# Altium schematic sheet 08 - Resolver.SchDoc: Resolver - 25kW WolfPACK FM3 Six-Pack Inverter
size 431 x 279 mm; Date: 07/2023; DocumentNumber: CRD25DA12N-FMC; Revision: 1.1; SheetNumber: 8; SheetTotal: 8; SheetSize: B
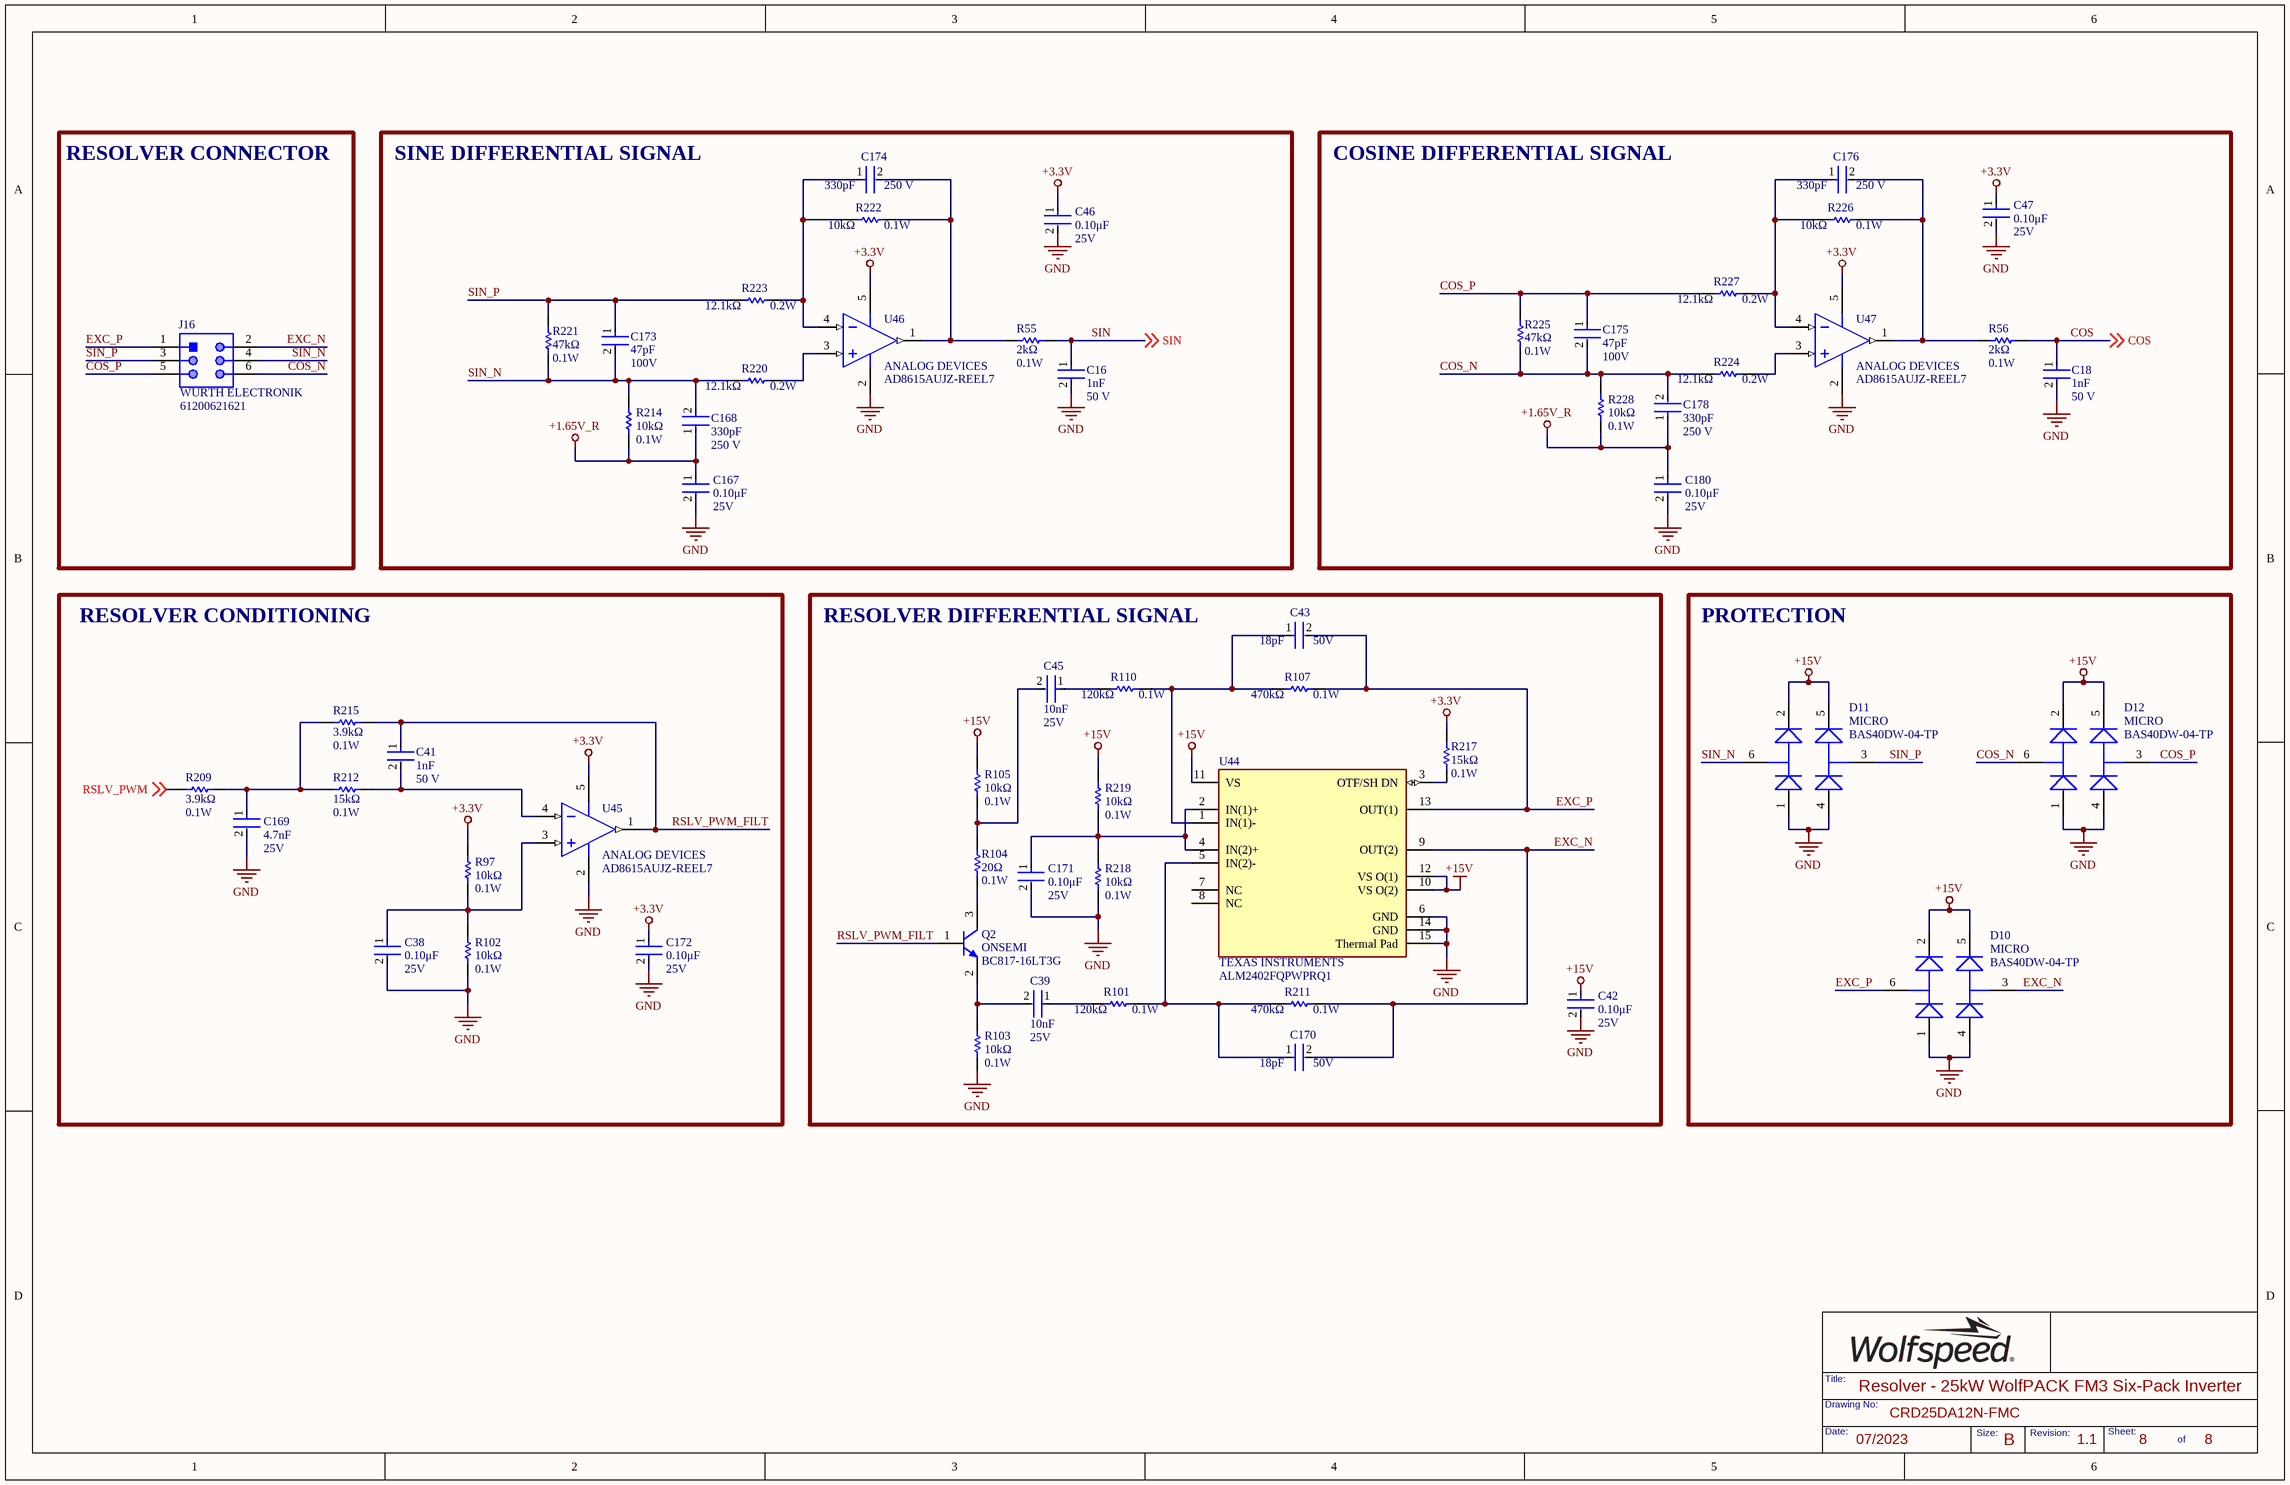
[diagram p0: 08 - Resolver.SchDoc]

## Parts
C16  Capacitance: 1nF  Voltage Rating: 50 V  [FP-C0603C-CF-IPC_B]  (hidden comment: C0603C102K5RACAUTO)
C18  Capacitance: 1nF  Voltage Rating: 50 V  [FP-C0603C-CF-IPC_B]  (hidden comment: C0603C102K5RACAUTO)
C38  Voltage Rating: 25V  Capacitance: 0.10μF  [FP-C0603C-CF-IPC_B]  (hidden comment: C0603C104K3RACTU)
C39  value 10nF  Voltage Rating: 25V  [FP-C0603C-CF-IPC_B]  (hidden comment: CL10B103KA8WPNC)
C41  Capacitance: 1nF  Voltage Rating: 50 V  [FP-C0603C-CF-IPC_B]  (hidden comment: C0603C102K5RACAUTO)
C42  Voltage Rating: 25V  Capacitance: 0.10μF  [FP-C0603C-CF-IPC_B]  (hidden comment: C0603C104K3RACTU)
C43  Capacitance: 18pF  Voltage Rating: 50V  [FP-C0603C-CF-IPC_B]  (hidden comment: 06035A180JAT2A)
C45  value 10nF  Voltage Rating: 25V  [FP-C0603C-CF-IPC_B]  (hidden comment: CL10B103KA8WPNC)
C46  Voltage Rating: 25V  Capacitance: 0.10μF  [FP-C0603C-CF-IPC_B]  (hidden comment: C0603C104K3RACTU)
C47  Voltage Rating: 25V  Capacitance: 0.10μF  [FP-C0603C-CF-IPC_B]  (hidden comment: C0603C104K3RACTU)
C167  Voltage Rating: 25V  Capacitance: 0.10μF  [FP-C0603C-CF-IPC_B]  (hidden comment: C0603C104K3RACTU)
C168  value 330pF  Voltage Rating: 250 V  [FP-C0603C-CF-IPC_B]  (hidden comment: C0603C331JAGAC7867)
C169  Voltage Rating: 25V  Capacitance: 4.7nF  [FP-C0603C-CF-IPC_B]  (hidden comment: C0603C472K3RAC7867)
C170  Capacitance: 18pF  Voltage Rating: 50V  [FP-C0603C-CF-IPC_B]  (hidden comment: 06035A180JAT2A)
C171  Voltage Rating: 25V  Capacitance: 0.10μF  [FP-C0603C-CF-IPC_B]  (hidden comment: C0603C104K3RACTU)
C172  Voltage Rating: 25V  Capacitance: 0.10μF  [FP-C0603C-CF-IPC_B]  (hidden comment: C0603C104K3RACTU)
C173  Capacitance: 47pF  Voltage Rating (DC): 100V  [FP-C0603C-CF-IPC_B]  (hidden comment: C0603C470J1GACTU)
C174  value 330pF  Voltage Rating: 250 V  [FP-C0603C-CF-IPC_B]  (hidden comment: C0603C331JAGAC7867)
C175  Capacitance: 47pF  Voltage Rating (DC): 100V  [FP-C0603C-CF-IPC_B]  (hidden comment: C0603C470J1GACTU)
C176  value 330pF  Voltage Rating: 250 V  [FP-C0603C-CF-IPC_B]  (hidden comment: C0603C331JAGAC7867)
C178  value 330pF  Voltage Rating: 250 V  [FP-C0603C-CF-IPC_B]  (hidden comment: C0603C331JAGAC7867)
C180  Voltage Rating: 25V  Capacitance: 0.10μF  [FP-C0603C-CF-IPC_B]  (hidden comment: C0603C104K3RACTU)
D10  Manufacturer Print: MICRO  [SOT65P222X120-6N]  (hidden comment: BAS40DW-04-TP)
D11  Manufacturer Print: MICRO  [SOT65P222X120-6N]  (hidden comment: BAS40DW-04-TP)
D12  Manufacturer Print: MICRO  [SOT65P222X120-6N]  (hidden comment: BAS40DW-04-TP)
J16  Manufacturer: WURTH ELECTRONIK  [61200621621]  (hidden comment: 61200621621)
Q2  Manufacturer: ONSEMI  [ONSC-SOT-23-3-318-08_V]  (hidden comment: BC817-16LT3G)
R55  Resistance: 2kΩ  Power Rating: 0.1W  [FP-MCR03-IPC_B]  (hidden comment: RT0603DRE072KL)
R56  Resistance: 2kΩ  Power Rating: 0.1W  [FP-MCR03-IPC_B]  (hidden comment: RT0603DRE072KL)
R97  Resistance: 10kΩ  Max Power Dissipation: 0.1W  [FP-MCR03-IPC_B]  (hidden comment: ERJ3EKF1002V)
R101  Max Power Dissipation: 0.1W  Resistance: 120kΩ  [FP-MCR03-IPC_B]  (hidden comment: RC0603FR-07120KL)
R102  Resistance: 10kΩ  Max Power Dissipation: 0.1W  [FP-MCR03-IPC_B]  (hidden comment: ERJ3EKF1002V)
R103  Resistance: 10kΩ  Max Power Dissipation: 0.1W  [FP-MCR03-IPC_B]  (hidden comment: ERJ3EKF1002V)
R104  Resistance: 20Ω  Power Rating: 0.1W  [FP-MCR03-IPC_B]  (hidden comment: RC0603JR-0720RL)
R105  Resistance: 10kΩ  Max Power Dissipation: 0.1W  [FP-MCR03-IPC_B]  (hidden comment: ERJ3EKF1002V)
R107  Resistance: 470kΩ  Power Rating: 0.1W  [FP-MCR03-IPC_B]  (hidden comment: RC0603FR-07470KL)
R110  Max Power Dissipation: 0.1W  Resistance: 120kΩ  [FP-MCR03-IPC_B]  (hidden comment: RC0603FR-07120KL)
R209  Resistance: 3.9kΩ  Power Rating: 0.1W  [FP-MCR03-IPC_B]  (hidden comment: ERJ3EKF3901V)
R211  Resistance: 470kΩ  Power Rating: 0.1W  [FP-MCR03-IPC_B]  (hidden comment: RC0603FR-07470KL)
R212  Resistance: 15kΩ  Power Rating: 0.1W  [FP-MCR03-IPC_B]  (hidden comment: ERA-3AED153V)
R214  Resistance: 10kΩ  Max Power Dissipation: 0.1W  [FP-MCR03-IPC_B]  (hidden comment: ERJ3EKF1002V)
R215  Resistance: 3.9kΩ  Power Rating: 0.1W  [FP-MCR03-IPC_B]  (hidden comment: ERJ3EKF3901V)
R217  Resistance: 15kΩ  Power Rating: 0.1W  [FP-MCR03-IPC_B]  (hidden comment: ERA-3AED153V)
R218  Resistance: 10kΩ  Max Power Dissipation: 0.1W  [FP-MCR03-IPC_B]  (hidden comment: ERJ3EKF1002V)
R219  Resistance: 10kΩ  Max Power Dissipation: 0.1W  [FP-MCR03-IPC_B]  (hidden comment: ERJ3EKF1002V)
R220  Resistance: 12.1kΩ  Max Power Dissipation: 0.2W  [FP-MCR03-IPC_B]  (hidden comment: ERJ-PB3B1212V)
R221  Resistance: 47kΩ  Power Rating: 0.1W  [FP-MCR03-IPC_B]  (hidden comment: RC0603FR-0747KL)
R222  Resistance: 10kΩ  Max Power Dissipation: 0.1W  [FP-MCR03-IPC_B]  (hidden comment: ERJ3EKF1002V)
R223  Resistance: 12.1kΩ  Max Power Dissipation: 0.2W  [FP-MCR03-IPC_B]  (hidden comment: ERJ-PB3B1212V)
R224  Resistance: 12.1kΩ  Max Power Dissipation: 0.2W  [FP-MCR03-IPC_B]  (hidden comment: ERJ-PB3B1212V)
R225  Resistance: 47kΩ  Power Rating: 0.1W  [FP-MCR03-IPC_B]  (hidden comment: RC0603FR-0747KL)
R226  Resistance: 10kΩ  Max Power Dissipation: 0.1W  [FP-MCR03-IPC_B]  (hidden comment: ERJ3EKF1002V)
R227  Resistance: 12.1kΩ  Max Power Dissipation: 0.2W  [FP-MCR03-IPC_B]  (hidden comment: ERJ-PB3B1212V)
R228  Resistance: 10kΩ  Max Power Dissipation: 0.1W  [FP-MCR03-IPC_B]  (hidden comment: ERJ3EKF1002V)
U44  Manufacturer: TEXAS INSTRUMENTS  [FP-PWP0014H-MFG]  (hidden comment: ALM2402FQPWPRQ1)
U45  Manufacturer: ANALOG DEVICES  [ADI-UJ-5_M]  (hidden comment: AD8615AUJZ-REEL7)
U46  Manufacturer: ANALOG DEVICES  [ADI-UJ-5_M]  (hidden comment: AD8615AUJZ-REEL7)
U47  Manufacturer: ANALOG DEVICES  [ADI-UJ-5_M]  (hidden comment: AD8615AUJZ-REEL7)

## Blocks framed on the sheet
RESOLVER CONNECTOR: J16
SINE DIFFERENTIAL SIGNAL: C16 C46 C167 C168 C173 C174 R55 R214 R220-R223 U46
COSINE DIFFERENTIAL SIGNAL: C18 C47 C175 C176 C178 C180 R56 R224-R228 U47
RESOLVER CONDITIONING: C38 C41 C169 C172 R97 R102 R209 R212 R215 U45
RESOLVER DIFFERENTIAL SIGNAL: C39 C42 C43 C45 C170 C171 Q2 R101 R103-R105 R107 R110 R211 R217-R219 U44
PROTECTION: D10-D12

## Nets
+1.65V_R: C167.1 C168.1 C178.1 C180.1 R214.1 R228.1
+3.3V: C46.1 C47.1 C172.1 R97.2 R217.2 U45.5(+V) U46.5(+V) U47.5(+V)
+15V: C42.1 D10.2(C1) D10.5(C2) D11.2(C1) D11.5(C2) D12.2(C1) D12.5(C2) R105.2 R219.2 U44.10(VS_O(2)) U44.11(VS) U44.12(VS_O(1))
GND: C16.2 C18.2 C38.2 C42.2 C46.2 C47.2 C167.2 C169.2 C171.2 C172.2 C180.2 D10.1(A1) D10.4(A2) D11.1(A1) D11.4(A2) D12.1(A1) D12.4(A2) R102.1 R103.1 R218.1 U44.6(GND) U44.14(GND) U44.15(Thermal_Pad) U45.2(-V) U46.2(-V) U47.2(-V)
COS: C18.1 R56.2 ; off-sheet COS
COS_N: C175.2 C178.2 D12.6(AC1) J16.6 R224.1 R225.1 R228.2
COS_P: C175.1 D12.3(AC2) J16.5 R225.2 R227.1
EXC_N: C170.2 D10.3(AC2) J16.2 R211.2 U44.9(OUT(2))
EXC_P: C43.2 D10.6(AC1) J16.1 R107.2 U44.13(OUT(1))
RSLV_PWM: R209.1 ; off-sheet RSLV_PWM
RSLV_PWM_FILT: C41.1 Q2.1(B) R215.2 U45.1(OUT)
SIN: C16.1 R55.2 ; off-sheet SIN
SIN_N: C168.2 C173.2 D11.6(AC1) J16.4 R214.2 R220.1 R221.1
SIN_P: C173.1 D11.3(AC2) J16.3 R221.2 R223.1
NetC38_1: C38.1 R97.1 R102.2 U45.3(+IN)
NetC39_1: C39.1 R101.1
NetC39_2: C39.2 Q2.2(E) R103.2
NetC41_2: C41.2 R212.1 U45.4(-IN)
NetC43_1: C43.1 R107.1 R110.2 U44.1(IN(1)-)
NetC45_1: C45.1 R110.1
NetC45_2: C45.2 R104.2 R105.1
NetC169_1: C169.1 R209.2 R212.2 R215.1
NetC170_1: C170.1 R101.2 R211.1 U44.5(IN(2)-)
NetC171_1: C171.1 R218.2 R219.1 U44.2(IN(1)+) U44.4(IN(2)+)
NetC174_1: C174.1 R222.2 R223.2 U46.4(-IN)
NetC174_2: C174.2 R55.1 R222.1 U46.1(OUT)
NetC176_1: C176.1 R226.2 R227.2 U47.4(-IN)
NetC176_2: C176.2 R56.1 R226.1 U47.1(OUT)
NetQ2_3: Q2.3(C) R104.1
NetR217_1: R217.1 U44.3(OTF/SH_DN)
NetR220_2: R220.2 U46.3(+IN)
NetR224_2: R224.2 U47.3(+IN)

Not connected (* = marked no-connect by the designer): U44 7(NC) 8(NC)

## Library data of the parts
C16 C18 C41 = CMP-2006-03716-2: CAP CER 1000PF 50V X7R 0603; Manufacturer: KEMET; Material: Ceramic; Automotive Grade: Grade 1; Value: 1nF; Tolerance: 0.1; Temperature Coefficient: 30ppm/°C
C38 C42 C46 C47 C167 C171 C172 C180 = CMP-2006-03057-2: CAP CER 0.1UF 25V X7R 0603; Manufacturer: KEMET; Value: 0.10μF; Material: Ceramic; Tolerance: 0.1; Temperature Coefficient: 30ppm/°C; Automotive Grade: Grade 1
C39 C45 = CL10B103KA8WPNC: CAP CER 10000PF 25V X7R 0603; Manufacturer: SAMSUNG; Tolerance: 10%
C43 C170 = 06035A180JAT2A: CAP CER 18PF 50V C0G/NP0 0603; Manufacturer: KYOCERA AVX; Dielectric Material: Ceramic; Tolerance: 5%; Dielectric: C0G; Insulation Resistance: 100GR; Temperature Coefficient: 30ppm/°C
C168 C174 C176 C178 = CMP-03020-020944-2: CAP CER 330PF 250V C0G/NP0 0603; Manufacturer: KEMET; Material: Ceramic; Temperature Coefficient: 30ppm/°C; Tolerance: 0.05; Automotive Grade: Grade 1; Temperature Characteristic: C0G
C169 = C0603C472K3RAC7867: CAP CER 4700PF 25V 10% X7R 0603; Manufacturer: KEMET; Manufacturer Part Number: C0603C472K3RACTU; Dielectric Material: Ceramic; Value: 4.7nF
C173 C175 = C0603C470J1GACTU: CAP CER 47PF 100V C0G/NP0 0603; Manufacturer: KEMET; Dielectric Material: Ceramic; Tolerance: 5%; Dielectric: C0G; Temperature Coefficient: 30ppm/°C; Dissipation Factor: 0.1%
D10-D12 = BAS40DW-04-TP: DIODE ARRAY SCHOTTKY 40V SOT363; Manufacturer_Name: Micro Commercial Components (MCC); Manufacturer: MICRO COMMERCIAL; Class: DIO
J16 = CMP-1502-00000-1: CONN HEADER VERT 6POS 2.54MM; Withstanding Voltage: 500VAC; Working Voltage: 250VAC; Pin Number: 6; Gender: Male; Contact Resistance: 20mOhm
Q2 = CMP-1048-00731-1: TRANS NPN 45V 0.5A SOT23-3; IC Continuous (A): 0.5; Packing: Tape and Reel; fT Min (MHz): 100
R55 R56 = RT0603DRE072KL: RES SMD 2K OHM 0.5% 1/10W 0603; Manufacturer: YAGEO; Temperature Coefficient: 50ppm/°C; Voltage Rating: 75V; Max Power Dissipation: 100mW; Voltage Rating (DC): 50V; Value: 2kΩ
R97 R102 R103 R105 R214 R218 R219 R222 R226 R228 = ERJ3EKF1002V: RES SMD 10K OHM 1% 1/10W 0603; Manufacturer: PANASONIC; Manufacturer Part Number: ERJ-3EKF1002V; Temperature Coefficient: 100ppm/°C; Power Rating: 100mW; Voltage Rating: 75V; Value: 10kΩ
R101 R110 = RC0603FR-07120KL: RES 120K OHM 1% 1/10W 0603; Manufacturer: YAGEO; Power Rating: 100mW; Voltage Rating: 50V; Temperature Coefficient: 100ppm/°C; Working Voltage: 75V; Value: 120kΩ
R104 = RC0603JR-0720RL: RES 20 OHM 5% 1/10W 0603; Manufacturer: YAGEO; Temperature Coefficient: 100ppm/°C; Voltage Rating (DC): 50V; Voltage Rating: 75V; Max Power Dissipation: 100mW; Value: 20Ω
R107 R211 = RC0603FR-07470KL: RES 470K OHM 1% 1/10W 0603; Manufacturer: YAGEO; Temperature Coefficient: 100ppm/°C; Voltage Rating: 50V; Max Power Dissipation: 100mW; Value: 470kΩ
R209 R215 = ERJ3EKF3901V: RES SMD 3.9K OHM 1% 1/10W 0603; Manufacturer: PANASONIC; Manufacturer Part Number: ERJ-3EKF3901V; Temperature Coefficient: 100ppm/°C; Voltage Rating: 75V; Max Power Dissipation: 100mW; Value: 3.9kΩ
R212 R217 = ERA-3AED153V: RES SMD 15K OHM 0.5% 1/10W 0603; Manufacturer: PANASONIC; Voltage Rating: 75V; Temperature Coefficient: 25ppm/°C; Max Power Dissipation: 100mW; Value: 15kΩ
R220 R223 R224 R227 = ERJ-PB3B1212V: RES SMD 12.1K OHM 0.1% 1/5W 0603; Manufacturer: PANASONIC; Temperature Coefficient: 50ppm/°C; Value: 12.1kΩ
R221 R225 = RC0603FR-0747KL: RES 47K OHM 1% 1/10W 0603; Manufacturer: YAGEO; Temperature Coefficient: 100ppm/°C; Voltage Rating: 50V; Max Power Dissipation: 100mW; Value: 47kΩ
U44 = CMP-04895-000282-1: IC POWER 2 CIRCUIT 14HTSSOP
U45-U47 = CMP-0384-02059-2: IC OPAMP GP 1 CIRCUIT TSOT23-5; Generic Part Number: AD8615; Iq/Amp: 1.7mA; V Span Max: 6V; Amplifiers Per Package: 1; Small Signal Bandwidth: 23MHz; Input Offset Voltage: 80uV; V Span Min: 2.7V; Slew Rate: 12V/us; Input Bias Current: 200fA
